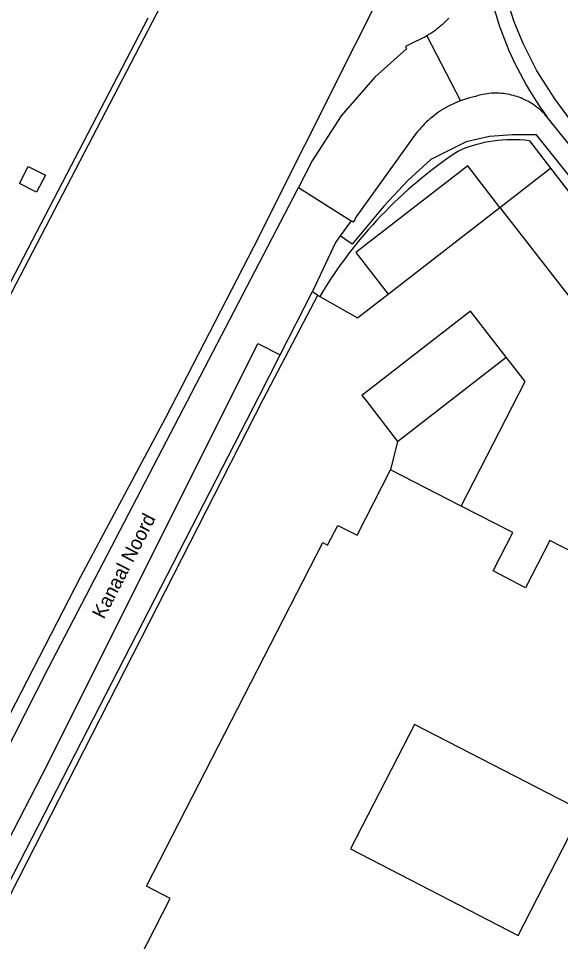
# Model space of a CAD drawing. Extents: x 194485 to 197793, y 468269 to 470822.
# Drawn here: x 194916.2 to 194962.7, y 470132.4 to 470211.6 of the extents above; entities that cross this region are included whole.
import ezdxf

# ---------------------------------------------------------------- set-up
doc = ezdxf.new("R2010")
doc.units = 0
for name, color, linetype in [('BGT grensvlak begroeid terreindeel LR', 7, 'Continuous'), ('BGT grensvlak onbegroeid terreindeel', 7, 'Continuous'), ('BGT grensvlak pand op maaiveld', 7, 'Continuous'), ('BGT grensvlak scheiding', 7, 'Continuous'), ('BGT grensvlak waterdeel', 7, 'Continuous'), ('BGT grensvlak wegdeel', 7, 'Continuous'), ('BGT tekst openbare ruimte label weg', 7, 'Continuous')]:
    doc.layers.add(name, color=color, linetype=linetype)

msp = doc.modelspace()

# ---------------------------------------------------------------- linework, layer by layer
at = {"layer": 'BGT grensvlak begroeid terreindeel LR'}
msp.add_line((194960.037, 470201.091), (194961.855, 470198.744), dxfattribs=at)
for centre, radius, start, end in [((194958.556, 470189.839), 11.349, 82.50364, 113.9358), ((194975.314, 470167.915), 38.723, 123.48177, 149.19404)]:
    msp.add_arc(centre, radius, start, end, dxfattribs=at)
at = {"layer": 'BGT grensvlak onbegroeid terreindeel'}
for p, q in [((194941.89, 470187.84), (194942.055, 470187.746)), ((194948.731, 470175.294), (194948.134, 470172.848))]:
    msp.add_line(p, q, dxfattribs=at)
for points in [[(194942.055, 470187.746), (194945.286, 470185.907), (194947.909, 470187.939)], [(194954.189, 470169.736), (194959.682, 470180.426), (194958.059, 470182.521)]]:
    msp.add_lwpolyline(points, dxfattribs=at)
at = {"layer": 'BGT grensvlak pand op maaiveld'}
msp.add_line((194954.189, 470169.736), (194948.134, 470172.848), dxfattribs=at)
for points in [[(194919.845, 470117.814), (194923.676, 470125.267), (194922.004, 470126.126), (194922.927, 470127.923), (194924.599, 470127.063), (194929.226, 470136.064), (194927.172, 470137.12), (194942.309, 470166.612), (194942.727, 470166.397), (194943.596, 470168.087), (194945.257, 470167.25), (194948.134, 470172.848)], [(194984.175, 470155.285), (194973.844, 470160.603), (194973.658, 470160.702), (194961.785, 470166.804), (194959.691, 470162.731), (194956.928, 470164.203), (194958.605, 470167.467), (194954.189, 470169.736)], [(194944.699, 470140.345), (194959.065, 470132.901), (194964.571, 470143.582), (194950.178, 470151.016), (194944.699, 470140.345)]]:
    msp.add_lwpolyline(points, dxfattribs=at)
at = {"layer": 'BGT grensvlak scheiding'}
for points in [[(194952.618, 470264.905), (194950.533, 470260.009), (194942.403, 470241.58), (194938.352, 470233.098), (194930.747, 470217.325), (194928.051, 470211.984), (194912.288, 470181.745), (194905.528, 470168.797), (194899.145, 470156.53), (194896.525, 470151.644), (194896.442, 470151.573), (194889.153, 470138.493), (194888.058, 470136.737), (194877.579, 470119.768), (194871.303, 470109.975), (194861.187, 470095.108), (194856.881, 470089.115), (194854.012, 470084.974)], [(194952.618, 470264.905), (194950.533, 470260.009), (194942.403, 470241.58), (194938.352, 470233.098), (194930.747, 470217.325), (194928.051, 470211.984), (194912.288, 470181.745), (194905.528, 470168.797), (194899.145, 470156.53), (194896.525, 470151.644), (194896.442, 470151.573), (194889.153, 470138.493), (194888.058, 470136.737), (194877.579, 470119.768), (194871.303, 470109.975), (194861.187, 470095.108), (194856.881, 470089.115), (194854.012, 470084.974)], [(194927.29, 470211.62), (194911.829, 470181.926), (194906.55, 470171.805), (194906.384, 470171.887), (194904.966, 470169.226), (194905.142, 470169.112), (194898.742, 470156.794), (194896.105, 470151.881), (194896.042, 470151.899), (194895.357, 470151.113), (194888.516, 470138.881), (194887.651, 470137.018), (194877.105, 470119.946), (194870.907, 470110.248), (194862.496, 470097.828), (194862.336, 470097.94), (194860.584, 470095.513), (194860.754, 470095.39), (194856.477, 470089.389), (194853.608, 470085.278)]]:
    msp.add_lwpolyline(points, dxfattribs=at)
at = {"layer": 'BGT grensvlak waterdeel'}
msp.add_lwpolyline([(194854.65, 470024.764), (194867.175, 470051.893), (194870.503, 470058.597), (194876.69, 470072.295), (194880.588, 470080.32), (194883.876, 470087.874), (194887.774, 470096.339), (194894.6, 470110.507), (194899.128, 470120.323), (194907.754, 470136.943), (194911.472, 470144.338), (194914.93, 470150.862), (194921.547, 470163.7), (194928.804, 470177.288), (194936.4, 470191.987), (194953.848, 470226.803)], dxfattribs=at)
at = {"layer": 'BGT grensvlak wegdeel'}
for p, q in [((194951.231, 470210.095), (194954.131, 470204.518)), ((194957.508, 470195.375), (194961.855, 470198.744)), ((194940.234, 470197.074), (194944.737, 470194.222)), ((194947.909, 470187.939), (194957.508, 470195.375)), ((194957.508, 470195.375), (194966.696, 470183.514)), ((194944.737, 470194.222), (194943.81, 470192.945)), ((194938.657, 470182.728), (194941.44, 470188.166)), ((194941.44, 470188.166), (194941.89, 470187.84)), ((194948.731, 470175.294), (194958.059, 470182.521))]:
    msp.add_line(p, q, dxfattribs=at)
for points in [[(194980.103, 470182.186), (194971.719, 470192.904), (194967.463, 470198.054), (194963.962, 470202.328), (194962.223, 470204.689), (194960.673, 470207.087), (194959.498, 470209.448), (194958.738, 470211.291), (194958.082, 470213.399), (194957.69, 470215.496), (194957.31, 470218.318), (194957.202, 470221.395), (194957.651, 470224.332), (194958.365, 470227.074), (194959.402, 470229.838), (194960.334, 470232.349), (194964.43, 470242.629), (194967.101, 470249.367), (194974.852, 470268.643)], [(194953.118, 470211.623), (194952.98, 470211.475), (194952.837, 470211.331), (194952.691, 470211.19), (194952.542, 470211.053), (194952.389, 470210.919), (194952.233, 470210.79), (194952.074, 470210.664), (194951.911, 470210.542), (194951.746, 470210.425), (194951.578, 470210.311), (194951.407, 470210.202), (194951.231, 470210.095)], [(194951.231, 470210.095), (194951.058, 470209.996), (194950.879, 470209.899), (194950.698, 470209.807), (194950.515, 470209.72), (194950.33, 470209.637), (194949.411, 470209.174), (194949.423, 470209.089), (194949.485, 470208.973), (194946.778, 470206.566), (194943.887, 470203.243), (194941.411, 470199.369), (194940.234, 470197.074)], [(194954.131, 470204.518), (194953.969, 470204.462), (194953.779, 470204.384), (194953.762, 470204.376)], [(194961.572, 470203.115), (194961.463, 470203.242), (194961.35, 470203.365), (194961.234, 470203.485), (194961.115, 470203.602), (194960.992, 470203.715), (194960.865, 470203.825), (194960.736, 470203.931), (194960.604, 470204.033), (194960.468, 470204.131), (194960.33, 470204.225), (194960.19, 470204.316), (194960.046, 470204.402), (194959.901, 470204.484), (194959.753, 470204.561), (194959.602, 470204.634), (194959.45, 470204.703), (194959.296, 470204.768), (194959.14, 470204.827), (194958.982, 470204.883), (194958.823, 470204.934), (194958.662, 470204.98), (194958.5, 470205.021), (194958.33, 470205.059), (194958.159, 470205.092), (194957.988, 470205.12), (194957.815, 470205.142), (194957.642, 470205.159), (194957.468, 470205.172), (194957.295, 470205.178), (194957.121, 470205.18), (194956.947, 470205.176), (194956.773, 470205.167), (194956.6, 470205.153), (194956.427, 470205.133), (194956.255, 470205.109), (194956.083, 470205.079), (194955.913, 470205.044), (194955.743, 470205.004), (194955.576, 470204.958), (194955.409, 470204.908), (194954.905, 470204.782), (194954.131, 470204.518)], [(194953.762, 470204.376), (194953.591, 470204.302), (194953.406, 470204.215), (194953.222, 470204.124), (194953.04, 470204.029), (194952.861, 470203.929), (194952.684, 470203.825), (194952.51, 470203.717), (194952.338, 470203.605), (194952.164, 470203.485), (194951.993, 470203.362), (194951.825, 470203.234), (194951.66, 470203.102), (194951.498, 470202.966), (194951.34, 470202.826), (194951.185, 470202.682), (194951.034, 470202.535), (194950.886, 470202.384), (194950.742, 470202.229), (194950.602, 470202.071), (194950.465, 470201.91), (194950.333, 470201.745), (194945.101, 470194.442), (194945.056, 470194.324), (194944.918, 470194.107), (194944.737, 470194.222)], [(194967.781, 470195.428), (194966.062, 470197.55), (194961.572, 470203.115)], [(194980.824, 470176.487), (194978.008, 470180.003), (194972.171, 470187.227), (194966.609, 470194.156), (194960.639, 470201.596), (194958.575, 470201.593), (194956.615, 470201.475), (194954.618, 470200.996), (194951.593, 470199.498), (194949.614, 470197.677), (194947.548, 470195.49), (194944.833, 470192.222), (194943.81, 470192.945)], [(194917.04, 470198.9), (194918.514, 470198.151), (194917.76, 470196.681), (194916.277, 470197.426), (194917.04, 470198.9)], [(194957.508, 470195.375), (194954.752, 470198.933), (194945.153, 470191.496), (194947.909, 470187.939)], [(194961.855, 470198.744), (194971.044, 470186.882), (194966.696, 470183.514)], [(194918.744, 470155.8), (194940.154, 470196.91), (194940.234, 470197.074)], [(194943.81, 470192.945), (194943.397, 470192.376), (194941.44, 470188.166)], [(194909.196, 470124.088), (194937.238, 470178.939), (194941.89, 470187.84)], [(194958.059, 470182.521), (194954.997, 470186.473), (194945.669, 470179.247), (194945.991, 470178.831), (194948.731, 470175.294)], [(194909.868, 470126.749), (194908.355, 470127.575), (194918.706, 470147.642), (194936.731, 470183.691), (194938.657, 470182.728)], [(194909.868, 470126.749), (194919.502, 470145.396), (194936.839, 470179.178), (194938.657, 470182.728)], [(194891.652, 470100.866), (194902.161, 470123.541), (194908.95, 470136.524), (194918.744, 470155.8)]]:
    msp.add_lwpolyline(points, dxfattribs=at)
for centre, radius, start, end in [((194990.366, 470221.938), 34.685, 183.07436, 198.52872), ((194985.422, 470220.603), 29.574, 199.11935, 216.25051)]:
    msp.add_arc(centre, radius, start, end, dxfattribs=at)

# ---------------------------------------------------------------- texts
at = {"layer": 'BGT tekst openbare ruimte label weg'}
msp.add_text('Kanaal Noord', height=1.2, rotation=62.8, dxfattribs=at).set_placement((194923.527, 470159.979))

doc.saveas('drawing.dxf')
